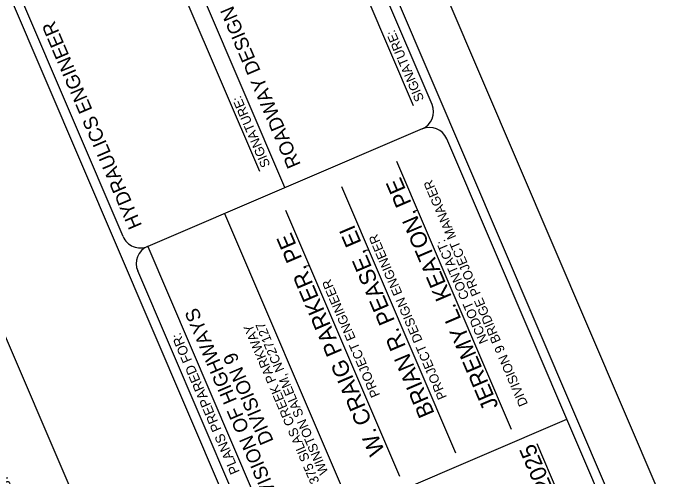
# Model space of a CAD drawing. Extents: x 1550250 to 1553210, y 808906 to 812497.
# Drawn here: x 1551945 to 1552554, y 811095 to 811523 of the extents above; entities that cross this region are included whole.
import ezdxf

# ---------------------------------------------------------------- set-up
doc = ezdxf.new("R2010")
doc.units = 0
for name, color, linetype in [('P_RDY_DSN_Text', 7, 'Continuous'), ('Scratch_Level_0', 7, 'Continuous'), ('Sheet Data Field CELL', 7, 'Continuous'), ('Sheet Title CELL', 7, 'Continuous'), ('Sheet_Plan_CELL', 7, 'Continuous'), ('Sheet_Title_CELL', 7, 'Continuous')]:
    doc.layers.add(name, color=color, linetype=linetype)

msp = doc.modelspace()

# ---------------------------------------------------------------- linework, layer by layer
at = {"layer": 'Scratch_Level_0'}
msp.add_line((1553148.39, 809662.7), (1551994.42, 812358.57), dxfattribs=at)
at = {"layer": 'Sheet Title CELL'}
for p, q in [((1552405.26, 811138.71), (1552299.2, 811386.49)), ((1552353.64, 811116.94), (1552248.34, 811362.99)), ((1552140.03, 811338.35), (1552347.05, 810854.67)), ((1552302.02, 811095.17), (1552196.72, 811341.22)), ((1552069.04, 811307.96), (1552276.08, 810824.29)), ((1552170.86, 811026.08), (1552456.31, 811148.27)), ((1552428.38, 811125.81), (1552505.6, 810945.42))]:
    msp.add_line(p, q, dxfattribs=at)
at = {"layer": 'Sheet_Plan_CELL'}
msp.add_lwpolyline([(1551190.18, 811336.14), (1551800.19, 809911.05), (1552391.43, 810164.14), (1551781.41, 811589.22)], close=True, dxfattribs=at)
at = {"layer": 'Sheet_Title_CELL'}
for p, q in [((1553086.33, 809698.16), (1551983.97, 812273.45)), ((1552747.76, 809656.43), (1551686.13, 812136.57)), ((1552195.84, 811362.24), (1552046.65, 811710.76)), ((1552314.58, 811437.93), (1552218.55, 811662.33)), ((1552046.33, 811317), (1551910.72, 811633.8)), ((1552172.46, 811377.09), (1552076.42, 811601.49)), ((1552322.72, 811416.55), (1552068.99, 811307.94)), ((1552322.72, 811416.55), (1552068.99, 811307.94)), ((1552253.37, 810833.33), (1552059.9, 811285.29))]:
    msp.add_line(p, q, dxfattribs=at)
for points in [[(1552331.77, 811439.19), (1552196.16, 811756)], [(1552538.81, 810955.52), (1552345.37, 811407.48)]]:
    msp.add_lwpolyline(points, dxfattribs=at)
for centre, start, end in [((1552315.84, 811432.38), 293.1736, 23.1736), ((1552329.42, 811400.66), 23.1736, 113.1736), ((1552062.11, 811323.77), 203.1736, 293.1736), ((1552075.69, 811292.05), 113.1736, 203.1736)]:
    msp.add_arc(centre, 17.25, start, end, dxfattribs=at)

# ---------------------------------------------------------------- texts
at = {"layer": 'P_RDY_DSN_Text'}
for s, p in [('END CONSTRUCTION', (1551964.55, 811002.16)), ('-Y- STA. 19+93.66', (1551976.96, 811007.48))]:
    msp.add_text(s, height=10, rotation=113.1736, dxfattribs=at).set_placement(p)
at = {"layer": 'Sheet Data Field CELL'}
for s, rotation, p in [('JEREMY L. KEATON, PE', 113.1736, (1552393.38, 811160.42)), ('BRIAN R. PEASE, EI', 113.1736, (1552334.27, 811153.64)), ('W. CRAIG PARKER, PE', 113.1736, (1552288.33, 811118.6)), ('FEBRUARY 18, 2025', 113.17595, (1552502.01, 810948.27))]:
    msp.add_text(s, height=15.0939, rotation=rotation, dxfattribs=at).set_placement(p)
at = {"layer": 'Sheet Title CELL'}
for s, height, rotation, p in [('DIVISION 9 BRIDGE PROJECT MANAGER', 8.6241, 113.1736, (1552420.47, 811162.33)), ('PROJECT DESIGN ENGINEER', 8.6241, 113.1736, (1552345.57, 811168.68)), ('NCDOT CONTACT:', 8.6241, 113.1736, (1552383.79, 811220.31)), ('PROJECT ENGINEER', 8.6241, 113.1736, (1552283.81, 811170.59)), ('DIVISION OF HIGHWAYS', 12.9377, 113.17595, (1552194.88, 811064.85)), ('375 SILAS CREEK PARKWAY', 8.6251, 113.17595, (1552227.8, 811090.65)), ('WINSTON SALEM, NC27127', 8.6251, 113.17595, (1552236.01, 811099.17)), ('PLANS PREPARED FOR:', 8.9701, 113.17595, (1552154.19, 811099.65)), ('DIVISION 9', 12.938, 113.17595, (1552185.59, 811128.11))]:
    msp.add_text(s, height=height, rotation=rotation, dxfattribs=at).set_placement(p)
at = {"layer": 'Sheet_Title_CELL'}
for s, height, p in [('ROADWAY DESIGN ENGINEER', 12.9365, (1552210.67, 811383.56)), (' HYDRAULICS ENGINEER', 12.9375, (1552065.89, 811322.86)), ('SIGNATURE:', 8.624, (1552324.6, 811443.91)), ('SIGNATURE:', 8.624, (1552182.47, 811383.07))]:
    msp.add_text(s, height=height, rotation=113.1736, dxfattribs=at).set_placement(p)

doc.saveas('drawing.dxf')
